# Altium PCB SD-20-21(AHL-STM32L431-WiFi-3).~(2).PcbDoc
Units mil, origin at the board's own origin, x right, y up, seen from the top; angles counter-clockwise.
Board outline 1905.3 x 2159.95 mil, 2 copper layers (Top Layer, Bottom Layer); 48 components, 77 nets, 281 pads, 181 vias.
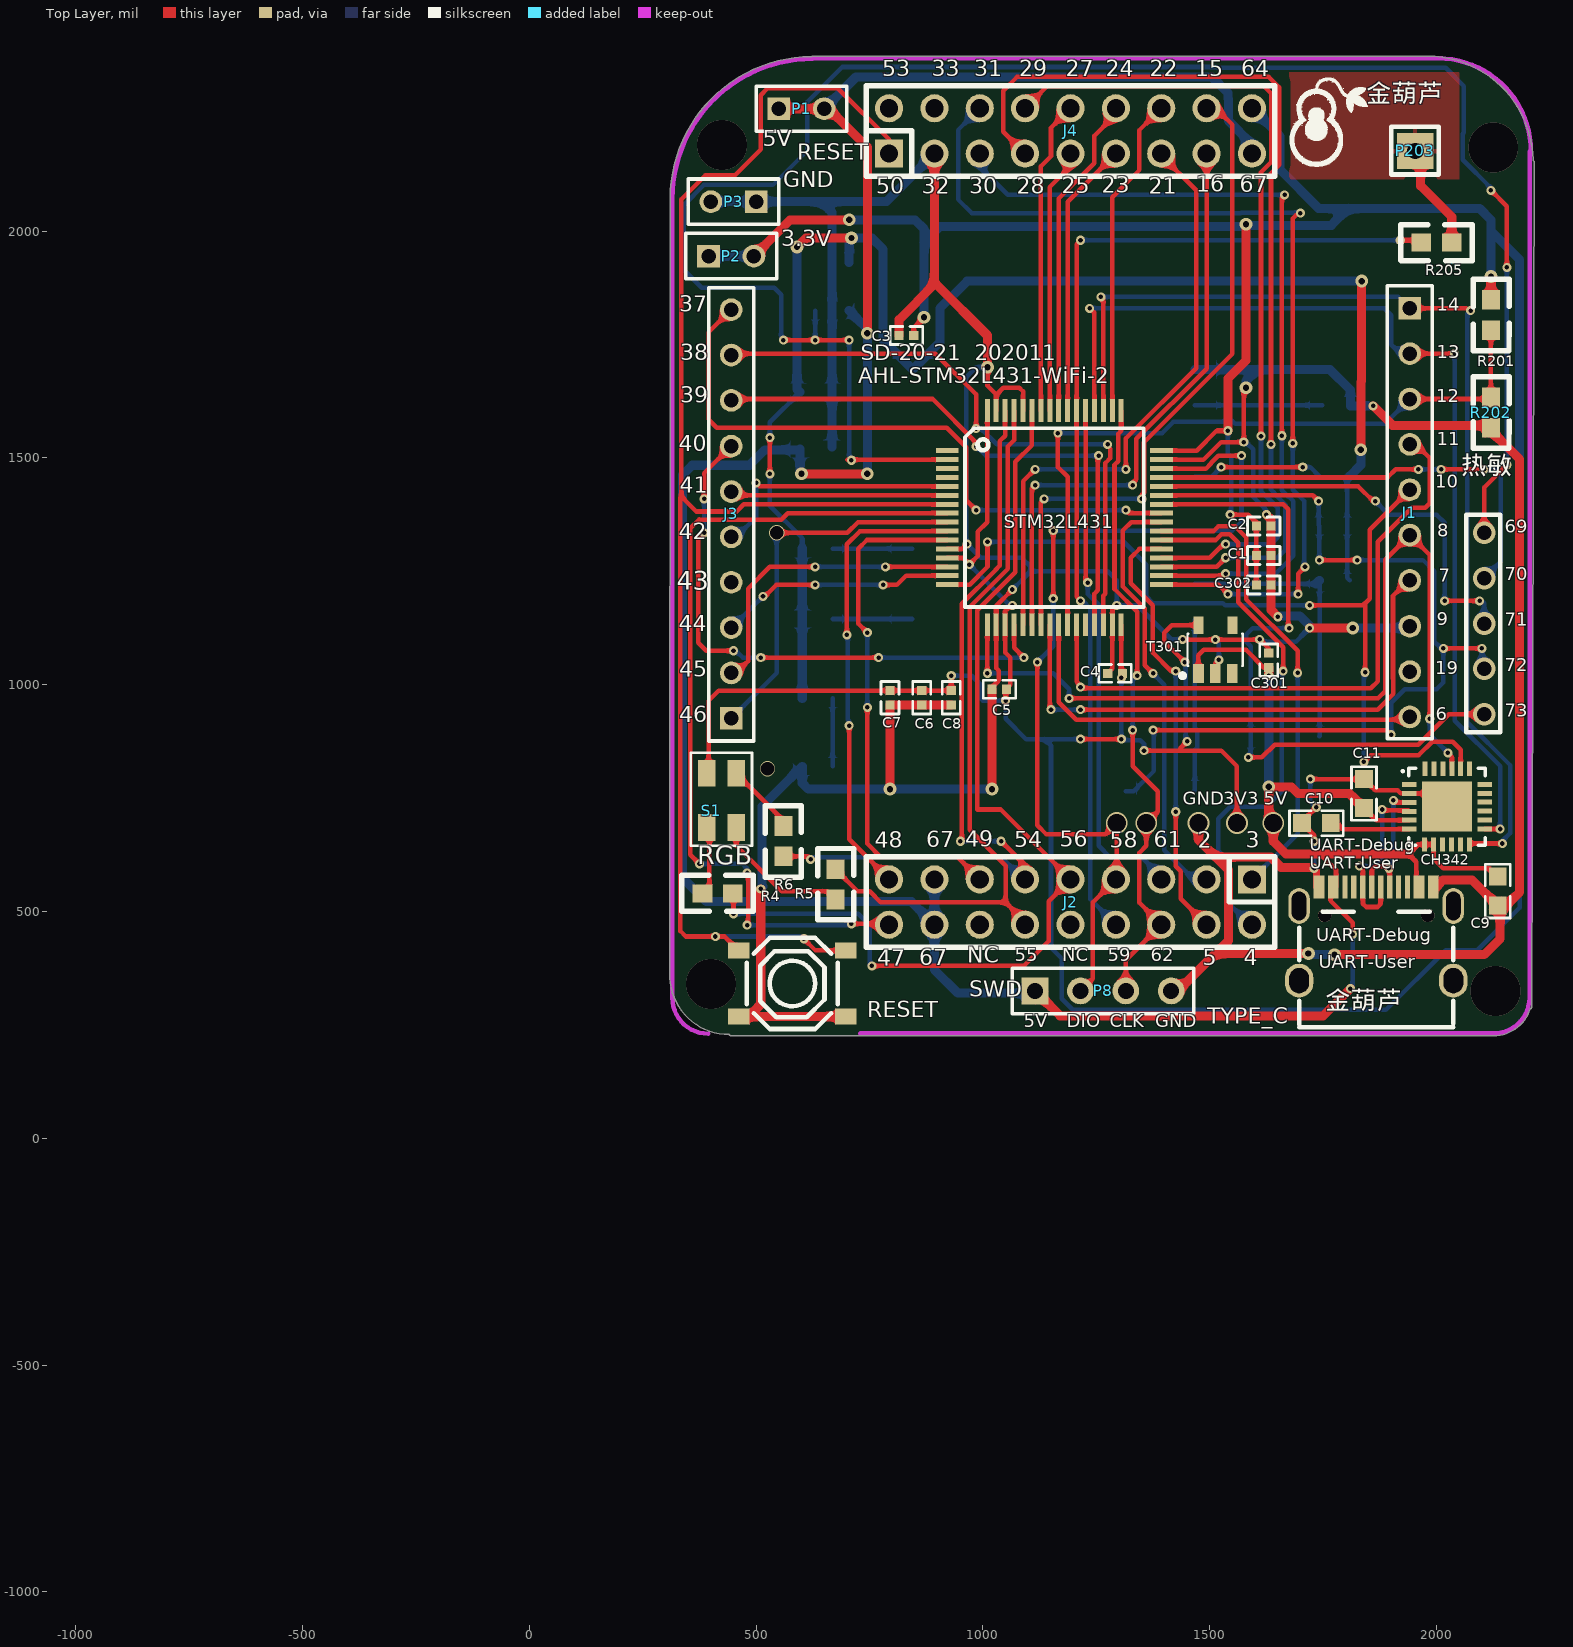
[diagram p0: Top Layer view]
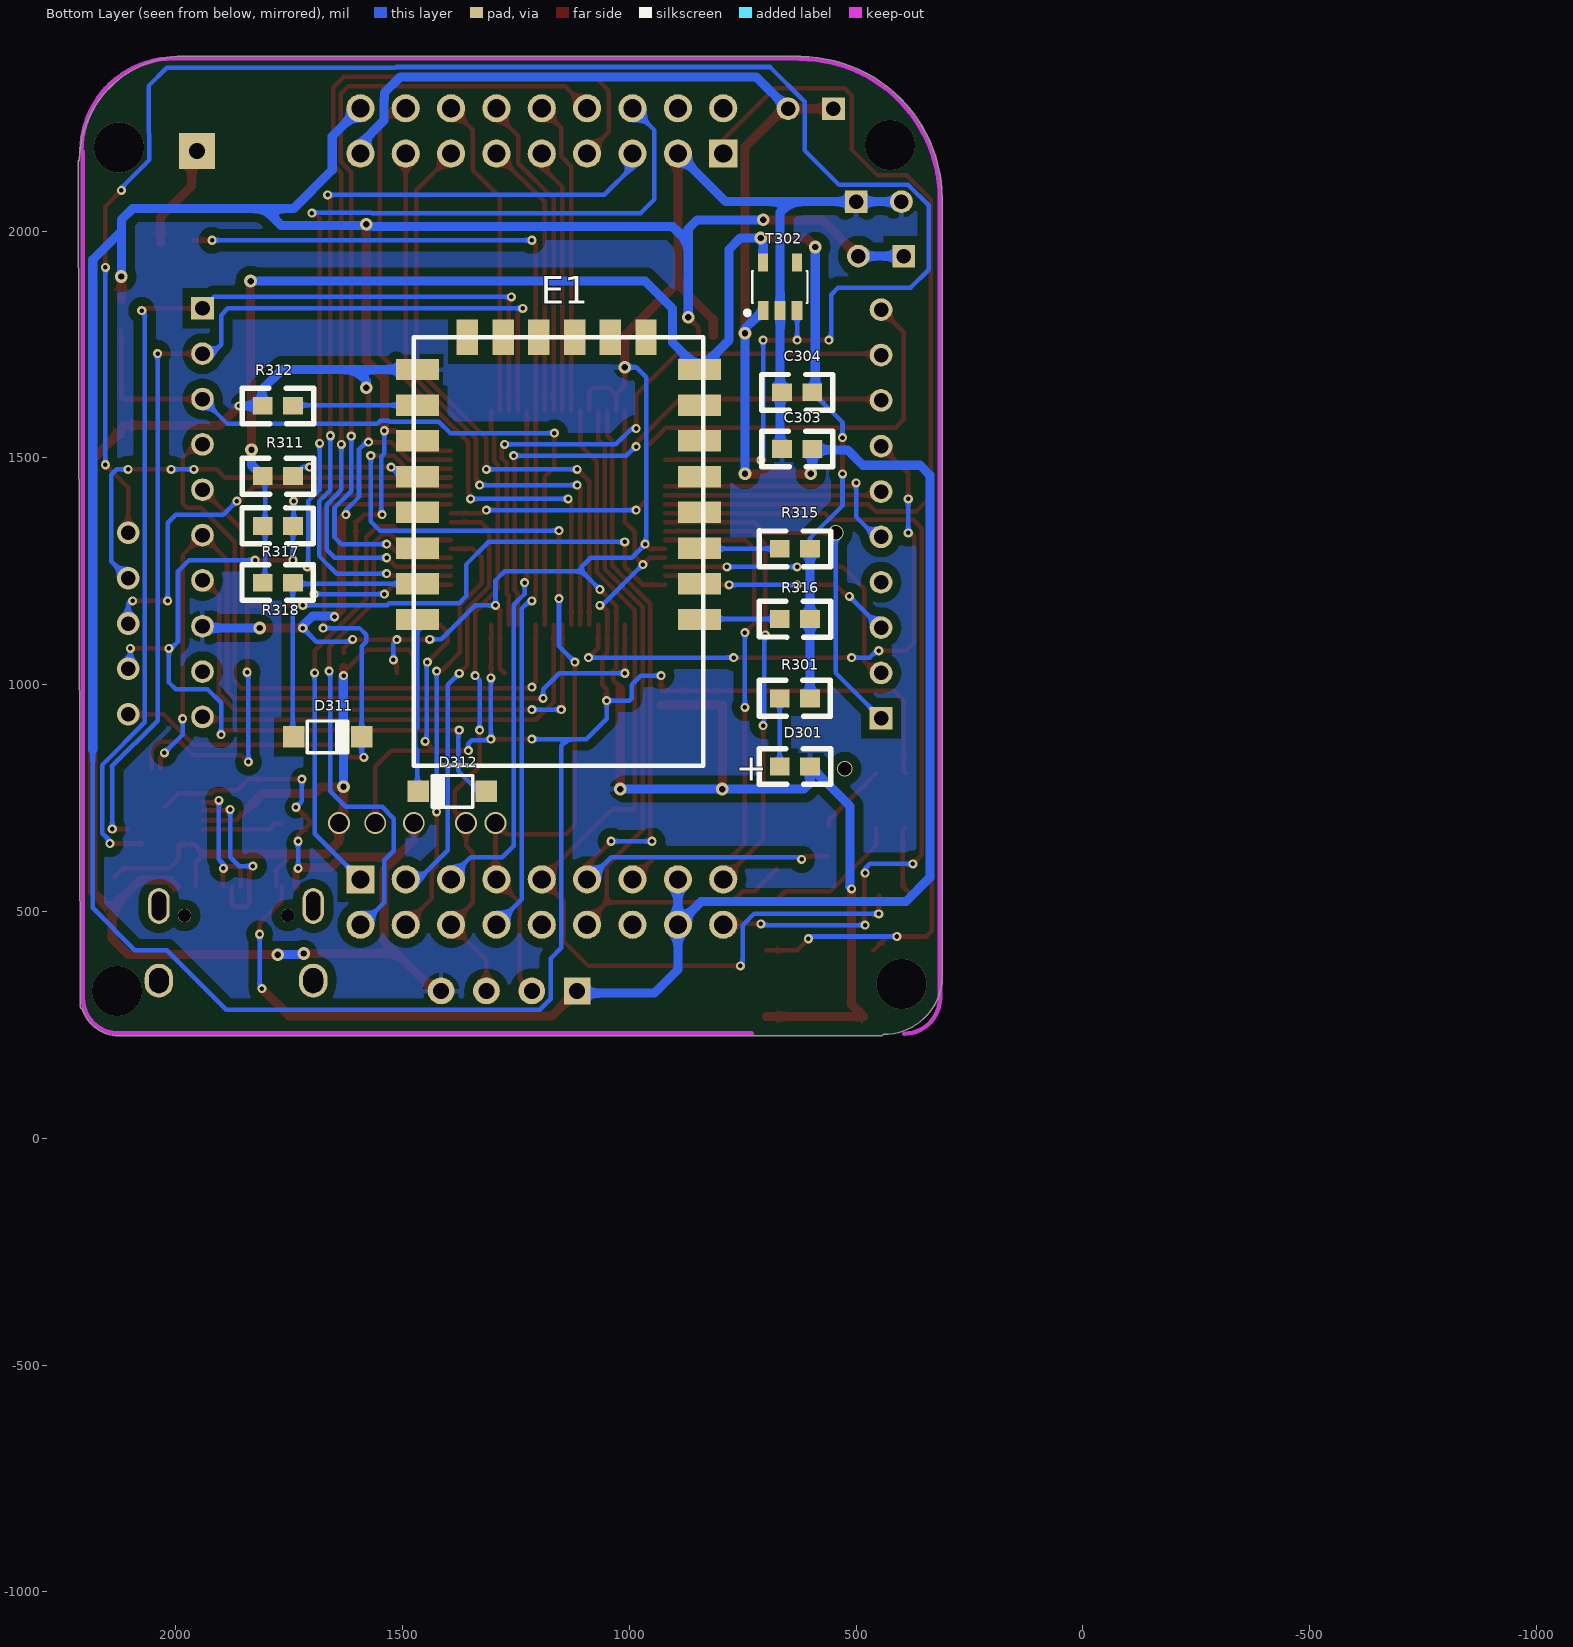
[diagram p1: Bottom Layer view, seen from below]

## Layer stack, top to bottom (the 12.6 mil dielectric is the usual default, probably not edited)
Top Solder: solder mask 0.4, Solder Resist, Dk 3.5
Top Layer: signal copper 1.4
Dielectric1: dielectric 12.6, FR-4, Dk 4.8
Bottom Layer: signal copper 1.4
Bottom Solder: solder mask 0.4, Solder Resist, Dk 3.5

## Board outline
309.97,365.12 ccw(c439.59,358.77) 440.44,229 ccw(c445,231.08) 445,226.07 2125.67,226.07 ccw(c2125.72,310.36) 2206.15,285.12 ccw(c2205,290) 2210.01,289.99 2215.26,2151.88 ccw(c2210.24,2151.89) 2215.26,2151.89 ccw(c2210.24,2151.89) 2212.77,2156.22 ccw(c1979.32,2152.54) 1980.39,2386.01 ccw(c1980.37,2381) 1979.86,2385.99 ccw(c1979.32,2381) 1979.32,2386.01 625,2386.01 ccw(c625,2381) 621.99,2385.01 ccw(c624.15,2071.15) 310.29,2071.96 ccw(c315.24,2071.2) 310.23,2071.2

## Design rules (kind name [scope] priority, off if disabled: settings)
Clearance Clearance_1 [All] p1: gap=7
HoleSize [All] p1: absolutevalues=TRUE maxlimit=200 minlimit=1 maxpercent=80.000 minpercent=20.000
MinimumSolderMaskSliver [All] p1: minsoldermaskwidth=0
PolygonConnect [All] p1: connectstyle=Relief reliefconductorwidth=10 reliefentries=4 polygonreliefangle="90 Angle" airgapwidth=10
RoutingVias [All] p1: holewidth=10 width=20 viastyle="Through Hole" minholewidth=10 minwidth=20 maxholewidth=10 maxwidth=20
SilkToSilkClearance [All] p1: silktosilkclearance=0
SilkToSolderMaskClearance [IsPad] p1: minsilkscreentomaskgap=0 clearancetoexposedcopper=TRUE
SolderMaskExpansion [All] p1: expansion=4
UnpouredPolygon [All] p1: allowunpoured=FALSE
Width [All] p1: maxlimit=20 minlimit=10 preferedwidth=10
25 further rules are at their usual default settings.

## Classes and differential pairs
component class 01_STM32L431_HardMinSys: C1 C5 C6 C7 C8 C9 STM32L431
component class 02_interface: C9 C301 C302 J1 J2 J3 P1 P2 P3 P203 R4 R5 R6 R201 R202 R205 S1 T301
component class 03_Wi-Fi-ESP8266: D201 D202 D301 R203 R204 R206 R301 T302

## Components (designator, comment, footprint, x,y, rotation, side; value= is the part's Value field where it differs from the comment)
C1 "Cap" 0402 1635,1285 r180 top (schematic designator C101)
C2 "Cap" 0402 1635,1350 r180 top (schematic designator C102)
C3 "Cap" 0402 815,1770 r0 top (schematic designator C103)
C4 "Cap" 0402 1275,1025 r0 top (schematic designator C104)
C5 "Cap" 0402 1020,990 r0 top (schematic designator C105)
C6 "Cap" 0402 865,955 r90 top (schematic designator C106)
C7 "Cap" 0402 795,955 r90 top (schematic designator C107)
C8 "Cap" 0402 930,955 r90 top (schematic designator C108)
C9 "Cap" 0603#1 2135,545 r270 top (schematic designator C4)
C10 "Cap" 0603#1 1735,695 r0 top (schematic designator C2)
C11 "Cap" 0603#1 1840,760 r90 top (schematic designator C3)
C301 "0402" 0402 1630,1070 r270 top
C302 "0402" 0402 1635,1220 r180 top
C303 "0402" 0603#2 630,1520 r180 bottom
C304 "0402" 0603#2 630,1645 r180 bottom
CH342 "ch342" ch342 1940,780 r0 top (schematic designator ch342)
D301 "LED3" 0603+ 635,820 r180 bottom
D311 "MBR0520" SOD-123 1665,885 r0 bottom
D312 "MBR0520" SOD-123 1390,765 r180 bottom
E1 "ESP8266" ESP8266 1475,1695 r180 bottom
J1 "J1-2" HDR1X10#1 1941,1830 r270 top locked
J2 "J2-2" IDC2X9 1593,571 r180 top
J3 "J3-2" HDR1X10#2 445,926 r90 top locked
J4 "J4-2" IDC2X9 793,2171 r0 top
P1 "5V" HDR1X2 550,2270 r0 top
P2 "3.3V" HDR1X2 395,1945 r0 top
P3 "GND" HDR1X2 500,2065 r180 top
P8 "SWD接口" HDR1X4 1115,325 r0 top
P203 "TSI触摸键" TSI 1995,2130 r90 top
R4 "Res2" 0603#2 415,540 r180 top
R5 "Res2" 0603#2 675,560 r90 top
R6 "Res2" 0603#2 560,655 r270 top
R201 "Res2" 0603#2 2120,1815 r90 top
R202 "热敏" 0603#2 2120,1600 r90 top
R205 "Res2" 0603#2 2000,1975 r0 top
R301 "Res2" 0603#2 635,970 r0 bottom
R311 "Res2" 0603#2 1775,1460 r180 bottom
R312 "Res2" 0603#2 1775,1615 r180 bottom
R315 "*" 0603#2 635,1300 r180 bottom
R316 "*" 0603#2 635,1145 r180 bottom
R317 "Res2" 0603#2 1775,1350 r0 bottom
R318 "Res2" 0603#2 1775,1225 r0 bottom
RESET "复位按钮" RESET_KEY 560,365 r0 top (schematic designator RESET_1)
S1 "Single-Pole, Single-Throw Switch" LED3 420,750 r90 top
STM32L431 "STM32" LQFP64 1000,1530 r0 top
T301 "SOT-23-5" SOT-23-5 1515,1085 r0 top
T302 "SOT-23-5" SOT-23-5 665,1885 r180 bottom
TYPE_C "TYPE-C-31-M-12" TYPE_C 1865,420 r0 top (schematic designator TAPE_C)

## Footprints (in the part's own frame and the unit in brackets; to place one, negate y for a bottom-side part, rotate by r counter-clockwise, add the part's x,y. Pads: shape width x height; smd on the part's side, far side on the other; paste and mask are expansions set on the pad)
0402 [mm]
  rect 0.51x0.51 smd: 1(0,0) 2(0.82,0)
  silkscreen extent -0.5,-0.5 1.32,0.5
0603#1 [mm]
  rect 1x1 smd: 1(-0.81,0) 2(0.81,0)
  silkscreen extent -1.5,-0.7 1.5,0.7
0603#2 [mm]
  rect 1.1x1 smd: 1(-0.85,0) 2(0.85,0)
  silkscreen extent -1.99,-1.01 2,0.99
0603+ [mm]
  rect 1.1x1 smd: 1(-0.85,0) 2(0.85,0)
  silkscreen extent -1.99,-1.01 2,0.99
ch342 [mm]
  rect 2.8x2.8 smd: 0(2.108,-1.232)
  rect 0.8x0.28 smd: 1(0,0) 2(0,-0.5) 3(0,-1.001) 4(0,-1.499) 5(0,-1.999) 6(0,-2.499) 13(4.216,-2.489) 14(4.216,-1.989) 15(4.216,-1.488) 16(4.216,-0.991) 17(4.216,-0.49) 18(4.216,0.01)
  rect 0.28x0.8 smd: 7(0.864,-3.353) 8(1.364,-3.353) 9(1.864,-3.353) 10(2.362,-3.353) 11(2.863,-3.353) 12(3.363,-3.353) 19(3.378,0.889) 20(2.878,0.889) 21(2.377,0.889) 22(1.88,0.889) 23(1.379,0.889) 24(0.879,0.889)
  silkscreen extent -0.37,-3.39 4.26,0.91
ESP8266 [mm]
  rect 2.4x1.2 smd: 1(0.2,0) 2(0.2,-2) 3(0.2,-4) 4(0.2,-6) 5(0.2,-8) 6(0.2,-10) 7(0.2,-12) 8(0.2,-14) 9(16,-14) 10(16,-12) 11(16,-10) 12(16,-8) 13(16,-6) 14(16,-4) 15(16,-2) 16(16,0)
  rect 1.2x2 smd: 17(13,1.8) 18(11,1.8) 19(9,1.8) 20(7,1.8) 21(5,1.8) 22(3,1.8)
  silkscreen extent 0,-22.2 16.2,1.8
HDR1X2 [mil]
  rect 50x50 hole 32: 1(0,0)
  round 50 hole 32: 2(100,0)
  silkscreen extent -50,-50 150,50
HDR1X4 [mm] "Connector; Header; 4 Position"
  rect 1.5x1.5 hole 0.9: 1(0,0)
  round 1.5 hole 0.9: 2(2.54,0) 3(5.08,0) 4(7.62,0)
  silkscreen extent -1.27,-1.27 8.89,1.27
HDR1X10#1 [mil]
  rect 50x50 hole 32: 1(0,0)
  round 50 hole 32: 2(100,0) 3(200,0) 4(300,0) 5(400,0) 6(500,0) 7(600,0) 8(701,0) 9(801,0) 10(901,0)
  silkscreen extent -50,-50 949,50
HDR1X10#2 [mil]
  rect 50x50 hole 32: 1(0,0)
  round 50 hole 32: 2(100,0) 3(200,0) 5(400,0) 6(500,0) 7(600,0) 8(701,0) 9(801,0) 10(901,0)
  round 50 hole 32 paste+0: 4(300,0)
  silkscreen extent -50,-50 949,50
IDC2X9 [mil]
  round 62 hole 40: 1(0,100) 3(100,100) 4(100,0) 5(200,100) 6(200,0) 7(300,100) 8(300,0) 9(400,100) 10(400,0) 11(500,100) 12(500,0) 13(600,100) 14(600,0) 15(700,100) 16(700,0) 17(800,100) 18(800,0)
  rect 62x62 hole 40: 2(0,0)
  silkscreen extent -50,-50 850,150
LED3 [mil]
  round 40 on Top Overlay: 0(-110,74)
  rect 59.06x39.37 smd: 1(-65,29) 2(55,29) 3(55,-36) 4(-65,-36)
  silkscreen extent -105,-71 100,64
LQFP64 [mm]
  rect 1.27x0.28 smd: 1(-2.007,-0.356) 2(-2.007,-0.856) 3(-2.007,-1.356) 4(-2.007,-1.856) 5(-2.007,-2.356) 6(-2.007,-2.856) 7(-2.007,-3.356) 8(-2.007,-3.856) 9(-2.007,-4.356) 10(-2.007,-4.856) 11(-2.007,-5.356) 12(-2.007,-5.856) 13(-2.007,-6.356) 14(-2.007,-6.856) 15(-2.007,-7.356) 16(-2.007,-7.856) 33(9.993,-7.856) 34(9.993,-7.356) 35(9.993,-6.856) 36(9.993,-6.356) 37(9.993,-5.856) 38(9.993,-5.356) 39(9.993,-4.856) 40(9.993,-4.356) 41(9.993,-3.856) 42(9.993,-3.356) 43(9.993,-2.856) 44(9.993,-2.356) 45(9.993,-1.856) 46(9.993,-1.356) 47(9.993,-0.856) 48(9.993,-0.356)
  rect 0.28x1.27 smd: 17(0.243,-10.106) 18(0.743,-10.106) 19(1.243,-10.106) 20(1.743,-10.106) 21(2.243,-10.106) 22(2.743,-10.106) 23(3.243,-10.106) 24(3.743,-10.106) 25(4.243,-10.106) 26(4.743,-10.106) 27(5.243,-10.106) 28(5.743,-10.106) 29(6.243,-10.106) 30(6.743,-10.106) 31(7.243,-10.106) 32(7.743,-10.106) 49(7.743,1.894) 50(7.243,1.894) 51(6.743,1.894) 52(6.243,1.894) 53(5.743,1.894) 54(5.243,1.894) 55(4.743,1.894) 56(4.243,1.894) 57(3.743,1.894) 58(3.243,1.894) 59(2.743,1.894) 60(2.243,1.894) 61(1.743,1.894) 62(1.243,1.894) 63(0.743,1.894) 64(0.243,1.894)
  silkscreen extent -1.01,-9.11 8.99,0.89
RESET_KEY [mil]
  rect 47.2x35.4 smd: 1(-98.4,49.2)
  rect 47.2x35.5 smd: 2(137.82,49.25) 3(-98.4,-96.45) 4(137.82,-96.45)
  silkscreen extent -81,-124 120,77
SOD-123 [mm]
  rect 1.2x1.2 smd: 1(1.905,0) 2(-1.905,0)
  silkscreen extent -1.14,-0.89 1.14,0.89
SOT-23-5 [mm]
  rect 0.6x1.05 smd: 1(-1.016,-1.524) 2(-0.066,-1.524) 3(0.884,-1.524)
  rect 0.55x1 smd: 4(0.884,1.176) 5(-1.016,1.176)
  silkscreen extent -2.03,-1.78 1.47,0.7, body extent -1.5,-1.53 1.4,1.27, height 1.09
TSI [mil]
  rect 80x80 hole 35.43: 1(47,42)
  silkscreen extent -5,-10 100,95
TYPE_C [mm]
  oval 1.2x2 hole 0.8 slot 1.6 at 90 deg: 1(-4.269,2.343) 4(4.371,2.343)
  oval 1.6x1.9 hole 1.1 slot 1.4 at 90 deg: 2(-4.269,-1.837) 3(4.371,-1.837)
  rect 0.3x1.3 smd: A1(-3.299,3.411) A4(-2.499,3.411) A5(-1.199,3.411) A6(-0.199,3.411) A7(0.301,3.411) A8(1.3,3.412) A9(2.601,3.411) A12(3.401,3.411) B1(3.101,3.411) B4(2.301,3.411) B5(1.801,3.411) B6(0.801,3.411) B7(-0.699,3.411) B8(-1.699,3.412) B9(-2.199,3.411) B12(-2.999,3.411)
  round 0.75 hole 0.75 unplated: ""(-2.839,1.813) ""(2.941,1.813)
  silkscreen extent -4.27,-4.44 4.37,2.01

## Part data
C1 C2 C3 C4 C5 C6 C7 C8 C9 C10 C11: "Capacitor"
C301 C302 C303 C304: library part Cap, "Capacitor"
D301: "Typical BLUE SiC LED"
J1 J3: library part "Header 10", "Header, 10-Pin"
J2 J4: library part CON2X9
P1 P2 P3: library part "Header 2", "Header, 2-Pin"
P8: library part "Header 4", "Header, 4-Pin"
P203: library part Plug, "Plug"
R4 R5 R6 R201 R205 R301 R311 R312 R317 R318: "Resistor"
R202: library part Res1, "Resistor"
R315 R316: library part Res2, "Resistor"
RESET: library part RESET
S1: library part LED_3
T301 T302: "TPS70933"

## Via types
v1: diameter 20, hole 10, Top Layer to Bottom Layer, 146 vias
v2: diameter 28, hole 14, Top Layer to Bottom Layer, 19 vias
v3: diameter 47.99, hole 40, Top Layer to Bottom Layer, 5 vias
v4: diameter 50, hole 32, Top Layer to Bottom Layer, 5 vias
v5: diameter 110.11, hole 110.11, Top Layer to Bottom Layer, 4 vias
v6: diameter 34, hole 30, Top Layer to Bottom Layer, 2 vias

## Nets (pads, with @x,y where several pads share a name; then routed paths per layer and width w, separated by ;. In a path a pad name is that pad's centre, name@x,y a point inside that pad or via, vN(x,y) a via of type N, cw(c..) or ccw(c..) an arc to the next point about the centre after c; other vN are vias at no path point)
DN2: CH342.4 TYPE_C.A7 TYPE_C.B7 | length 393.3
  Top Layer w10: v1(1830,600) 1837.47,592.53 TYPE_C.B7 1837.47,517.53 1845,510 1870,510 1876.84,516.84 TYPE_C.A7 ; v1(1880,725) 1882,723 1914.11,723 1914.2,723.09 1937.91,723.09 CH342.4
  Bottom Layer w10: v1(1830,600) 1860,600 1880,620 v1(1880,725)
DP2: CH342.3 TYPE_C.A6 TYPE_C.B6 | length 317.5
  Top Layer w10: TYPE_C.A6 1857.16,592.16 1865,600 1890,600 1896.53,593.47 TYPE_C.B6 ; v1(1905,745) 1909.4,740.6 CH342.3
  Bottom Layer w10: v1(1895,595) 1890,600 1905,615 v1(1905,745)
GND: C1.1 C2.1 C3.1 C4.1 C5.1 C6.1 C7.1 C8.1 C9.2 C10.1 C11.2 C301.1 C302.1 C303.1 C304.1 CH342.0 CH342.2 D301.2 E1.1 J1.8 J4.4 P3.1 P3.2 P8.4 R202.1 R312.1 RESET.3 RESET.4 STM32L431.12 STM32L431.18 STM32L431.31 STM32L431.47 STM32L431.60 STM32L431.63 T301.2 T302.2 TYPE_C.A1 TYPE_C.A12 TYPE_C.B1 TYPE_C.B12 | length 10800.7
  Top Layer w10: STM32L431.12 954.46,1299.46 v1(965,1310) ; v2(1010,1700) 1010,1659.27 1029.27,1640 1029.27,1639.27 ; C5.1@1020,994.77 1035,1009.77 1035,1031.11 1029.27,1036.84 STM32L431.18 1029.27,1174.27 v1(1065,1210) ; STM32L431.63 1029.27,1639.27 ; STM32L431.60 1088.32,1646.68 1080,1655 1045,1655 1029.27,1639.27 ; C4.1 1285.17,1035.17 STM32L431.31 1285.17,1165.17 v1(1295,1175) ; STM32L431.47 1486.16,1496.32 1524.85,1535 v1(1575,1535) 1575,1650 v2(1580,1655) ; v1(1440,1100) 1440.39,1099.61 v1(1512.39,1099.61) 1609.61,1099.61 v1(1610,1100) 1630,1080 C301.1 ; T301.2 1512.4,1047.4 v1(1520,1055) ; v1(1721.89,791.89) C11.2 1864.89,767 1914.77,767 1921.47,760.3 CH342.2 1994.2,760.3 CH342.0 ; v1(1730,655) 1730,668.11 C10.1 1703.11,698.11 v1(1735,730) ; C9.2@2126.17,504.28 C9.2
  Top Layer w15: v1(1730,595) 1735.11,589.89 TYPE_C.A1
  Top Layer w20: v1(510,550) 510,295 483.55,268.55 RESET.4 ; v2(795,770) C7.1 C6.1 C8.1 ; C3.1 815,1805 893,1883 ; J4.4 893,1883 ; v2(1010,1700) 1010,1770 897,1883 893,1883 ; v2(1020,770) C5.1 ; P8.4 1430,325 1512.5,407.5 ; v3(1475,695) 1475,657.88 1512.88,620 ; v1(1625,1375) 1635,1365 C2.1 C1.1 C302.1 1635,1165 v1(1650,1150) ; v2(1717.5,407.5) 1512.5,407.5 ; v1(1720,1125) v2(1815,1125) ; v1@1727.5,597.5 1657.5,597.5 1635,620 1512.88,620 ; v2(1775,405) 2105,405 2140,440 2140,508.11 C9.2 ; v1(1860,1615) 1903,1572 2114.54,1572 R202.1 2120,1560 2183,1497 2183,543 2153.11,513.11 C9.2 ; TYPE_C.A12 2014.61,570 2078.11,570 C9.2 ; 1512.5,407.5 1541,436 1541,591.88 1512.88,620
  Bottom Layer w10: v2(1010,1700) 985,1700 963,1678 963,1312 v1(965,1310) 995,1280 1085,1280 1105,1260 1105,1250 ; v1(1065,1210) 1105,1250 ; v1(1440,1100) 1415,1100 1340,1175 v1(1295,1175) 1295,1230 1275,1250 1105,1250 ; v1(1512.39,1099.61) 1520,1092 v1(1520,1055) ; v1(1575,1535) 1580,1535 1596,1519 1596,1414 1625,1385 v1(1625,1375) ; v1@1610,1095 1690,1095 v1(1720,1125) ; v1(1721.89,791.89) 1721.89,743.11 v1(1735,730) ; v1(1730,595) v1(1730,655)
  Bottom Layer w20: P3.2 P3.1 643.5,2065 ; v1@515,555 513.27,556.73 513.27,731.73 D301.2 601.53,783.47 615,770 v2@790,770 ; C303.1@667.6,1524.13 T302.2 667.6,2040.9 643.5,2065 ; v2(795,770) v2@1010,770 ; J4.4 787,2065 643.5,2065 ; E1.1 1605,1695 ; v2(1580,1655) 1580,1670 1605,1695 ; v1(1650,1150) 1652,1152 1698,1152 1720,1130 v1(1720,1125) ; v2(1717.5,407.5) 1720,405 v2(1775,405) ; v2(1815,1125) 1937,1125 J1.8 ; v1@1850,1615 1810,1615 1810,1650 1765,1695 1605,1695
GNSS-ANT: J1.9
GSM-ANT: J4.3
NC: J2.13
NetC10_2: C10.2 CH342.6 | length 178.7
  Top Layer w10: C10.2 1780,695 1793.4,681.6 CH342.6
NetC109_2: STM32L431.4
NetC110_2: STM32L431.3
NetD201_2: 
NetD202_1: 
NetD301_1: D301.1 R301.2 | length 150
  Bottom Layer w10: D301.1 R301.2
NetD311_1: D311.1 E1.7 R318.1 | length 616.3
  Bottom Layer w10: E1.7 R318.1@1734.09,1222.56 ; D311.1@1741.54,886.54 1742,887 1742,1224.54 R318.1
  Bottom Layer w20: R318.1@1734.09,1222.56 R318.1@1741.54,1230
NetD312_2: D312.2 E1.8 | length 383.7
  Bottom Layer w10: D312.2 1467.13,767.13 1467.13,856.14 1472,861.01 1472,900.13 1467.13,905 E1.8
NetE1_2: E1.2 R312.2 | length 281
  Bottom Layer w10: E1.2 R312.2@1748.15,1616.26
NetE1_4: E1.4 R311.2 | length 281.5
  Top Layer w10: v1(1525,1480) v1@1695,1480
  Bottom Layer w10: E1.4 1503.78,1458.78 v1(1525,1480) ; v1(1705,1480) 1721.53,1480 R311.2
NetE1_9: E1.9 R316.1 | length 175.4
  Bottom Layer w10: R316.1 E1.9@843.9,1145
NetE1_11: E1.11 R315.1 | length 175.3
  Bottom Layer w10: R315.1 E1.11@843.78,1300
NetP203_1: P203.1 R205.2 | length 218.4
  Top Layer w20: P203.1@1965,2165 1965,2100 2033.47,2031.53 R205.2
NetR4_2: R4.2 S1.1 | length 158.9
  Top Layer w10: R4.2@381.54,535 R4.2 397,555.46 397,679 S1.1
NetR5_1: R5.1 S1.4 | length 307.8
  Top Layer w10: S1.4 456,645.54 556.54,545 656.54,545 R5.1
NetR6_1: R6.1 S1.3 | length 159.6
  Top Layer w10: S1.3 560,701 R6.1
P3V3: C1.2 C2.2 C3.2 C4.2 C5.2 C6.2 C7.2 C8.2 C302.2 J4.17 P2.1 P2.2 R201.2 S1.2 STM32L431.13 STM32L431.19 STM32L431.32 STM32L431.48 STM32L431.64 T301.5 | length 9790.8
  Top Layer w10: S1.2 395,809 395,965 417.28,987.28 C7.2 C6.2 C8.2 930,1010 ; C3.2 847.28,1787.28 v2(870,1810) ; STM32L431.13 955.22,1279.78 v1(970,1265) 988,1283 988,1337 1009.58,1358.58 STM32L431.64 ; v1(1050,965) 1050,990 1060,1000 1060,1060 1048.95,1071.05 STM32L431.19 1048.95,1162.96 v1@1060.99,1175 ; v1(1215,880) v1(1305,880) ; C4.2@1304.86,1027.43 STM32L431.32 ; v1(1355,855) 1435,855 ; STM32L431.48 1471,1516 1515,1560 v1(1540,1560) ; v1@1440,1055 1400,1095 1400,1115 1416.3,1131.3 T301.5 ; v1(1450,875) 1435,860 1435,855 ; v1(1545,1375) 1585,1375 1602.72,1357.28 C2.2 C1.2 C302.2 ; v3(1560,695) 1560,820 1525,855 1435,855
  Top Layer w20: P2.2 575,2025 v2(705,2025) ; v1(1540,1560) 1540,1675 1580,1715 v2(1580,2015) v2@1581,2015 ; R201.2 v2(2120,1900)
  Bottom Layer w10: v1(930,1020) 975,1020 995,1000 995,970 1000,965 v1(1050,965) 1050,925 1095,880 1135,880 ; v1(970,1265) 1055,1180 v1@1060,1180 ; v1(1215,880) 1135,880 ; v1(1305,1015) v1(1305,880) 1307,878 1347,878 1355,870 v1(1355,855) ; v1(1445,1050) 1447,1048 v1@1447,883 ; v1(1540,1560) 1540,1510 1547,1503 1547,1377 v1(1545,1375) ; 2183,857 2183,508 2090,415 2020,415 1888.47,283.47 1197.8,283.47 1173.47,307.8 1173.47,396.53 1150,420 1150,865 1135,880
  Bottom Layer w20: P2.1 P2.2 ; v2(705,2025) 850,2025 870,2005 870,1975 ; v2(870,1810) 870,1975 ; J4.17 1655,2209 1655,2135 1740,2050 1805,2050 ; v2(2120,1900) 2120,1995 ; 2183,857 2183,1937 2125,1995 2120,1995 ; 870,1975 905,2010 1575,2010 v2(1580,2015) 1582,2013 1768,2013 1805,2050 ; 1805,2050 2095,2050 2120,2025 2120,1995
  other v1: 1065,1175
P3V3_ME: C304.2 E1.16 R301.1 R311.1 R315.2 R316.2 R317.2 R318.2 T302.5 | length 3401.5
  Top Layer w10: v1(530,1465) v1(530,1545)
  Top Layer w20: v2(590,1965) 610,1985 v2(710,1985) ; v2(1833,1518) 1833,1668 1835,1670 v2(1835,1890)
  Bottom Layer w10: v1(530,1465) 530,1395 601.53,1323.47 R315.2 ; v1(530,1545) 530,1578.47 C304.2 ; R311.1@1803,1454.54 1803,1235.47 R318.2@1808.46,1230
  Bottom Layer w20: v2(590,1965) 590,1651.53 C304.2 ; R301.1 R315.2 ; T302.5 705,1980 v2(710,1985) 755,1985 780,1960 780,1760.08 E1.16 845.08,1695.08 905,1755 905,1830 965,1890 v2(1835,1890) ; R311.1@1803,1454.54 R311.1 1833,1484.54 v2(1833,1518)
P3V9: 
P5V: C9.1 C11.1 C301.2 C303.2 CH342.5 CH342.7 CH342.8 J2.15 J2.16 J4.18 P1.1 P1.2 P8.1 T301.1 T302.1 TYPE_C.A4 TYPE_C.A9 TYPE_C.B4 TYPE_C.B9 | length 7172.7
  Top Layer w10: T301.1 1475,1065 1487,1077 1580,1077 1619.28,1037.72 C301.2 ; 1745,625 1766.61,603.39 1778.42,591.58 TYPE_C.B9 ; TYPE_C.A4 1766.61,523.39 1815,475 v1(1815,450) ; C11.1 1866.81,701.3 CH342.5 ; TYPE_C.B4 1955.58,609.42 1938,627 1959,648 CH342.7 CH342.8 1993.7,616.3 2015,595 2116.89,595 C9.1
  Top Layer w20: P1.1 P1.2 660,2270 745,2185 v2@745,1785 ; v2(600,1465) v2(745,1465) ; P8.1 1170,270 1750,270 v1(1810,330) ; v1(1630,1020) C301.2 ; C11.1 1808.11,760 1695,760 1680,775 v2(1630,775) 1630,705 v3(1640,695) 1640,655 1668,627 1938,627
  Bottom Layer w10: v1(1810,330) 1815,335 v1(1815,450)
  Bottom Layer w20: v2@596.53,1468.47 C303.2 594.53,1518 519,1518 485,1484 359,1484 337.25,1462.25 337.25,575 390.25,522 842,522 J2.15 ; P1.2@650,2265 P1.2 720,2340 1505,2340 1540,2305 1540,2292.88 1541,2291.88 1541,2244 1593,2192 J4.18 ; T302.1 745,1785 v2(745,1775) v2(745,1465) ; J2.16 J2.15 ; P8.1 1110,320 945,320 893,372 J2.15 ; v2(1630,775) 1630,853.09 1630.62,853.71 1630.62,1019.38 v1(1630,1020)
PTA0: J3.2 STM32L431.14 | length 666.7
  Top Layer w10: J3.2 456,1026 482,1052 482,1212 530.09,1260.09 v1(630,1260.09) ; v1(785,1260.09) STM32L431.14
  Bottom Layer w10: v1(630,1260.09) v1(785,1260.09)
PTA1: J3.3 STM32L431.15 | length 522.5
  Top Layer w10: v1@517,1192.41 544.59,1220 v1(630,1220) ; v1(780,1220) 810,1220 830.41,1240.41 STM32L431.15
  Bottom Layer w10: J3.3 446,1126 v1(515,1195) ; v1(630,1220) v1(780,1220)
PTA2: CH342.20 J1.5 STM32L431.16 | length 2016.6
  Top Layer w10: STM32L431.16 970.72,1220.72 1010,1260 v1(1010,1315) ; v1(1720,1175) 1836.88,1175 1841.88,1180 1842.44,1179.44 ; v1(1840,830) 1855,845 1961.04,845 1990.52,874.48 2035.52,874.48 2053.3,856.7 CH342.20 ; v1(1842.44,1027.56) 1842.44,1179.44 ; J1.5 1853,1342 1853,1190 1842.44,1179.44
  Bottom Layer w10: v1(1010,1315) 1310,1315 1360,1265 1360,1195 1375,1180 1528.89,1180 1533.89,1175 v1(1720,1175) ; v1(1840,830) 1840,1025.12 v1(1842.44,1027.56)
PTA3: CH342.21 J1.6 STM32L431.17 | length 1945.1
  Top Layer w10: v1(1009.58,1025.42) STM32L431.17 ; v1(1190,970) 1870.96,970 1887,986.04 1887,1276 J1.6 1985,1286 v1(1985,925) ; v1(2025,850) 2033.6,841.4 CH342.21
  Bottom Layer w10: v1(1009.58,1025.42) 1154.58,1025.42 1190,990 v1(1190,970) ; v1(1985,925) 1985,890 v1(2025,850)
PTA4: J3.7 STM32L431.20 | length 1271.8
  Top Layer w10: v1@380,1335 372,1327 372,1093 390,1075 v1(450,1075) ; v1(385,1410) 385,1466 J3.7 ; v1(510,1060) v1(770,1060) ; STM32L431.20 1068.64,1081.36 v1(1090,1060)
  Bottom Layer w10: v1(385,1335) 385,1400 ; v1(450,1075) 455,1075 470,1060 v1(510,1060) ; v1@762,1060 v1(770,1060) v1(1090,1060)
PTA5: J4.14 STM32L431.21 | length 1346
  Top Layer w10: STM32L431.21 1088.32,1448.32 v1(1115,1475) ; v1(1315,1475) 1315,1543.08 1470,1698.08 1470,2090 1393,2167 J4.14
  Bottom Layer w10: v1(1115,1475) v1(1315,1475)
PTA6: J4.16 STM32L431.22 | length 1324.3
  Top Layer w10: STM32L431.22 1108.01,1433.01 v1(1115,1440) ; v1(1330,1440) 1330,1445 1338,1453 1338,1542.04 1493,1697.04 J4.16
  Bottom Layer w10: v1(1115,1440) v1(1330,1440)
PTA7: J4.15 STM32L431.23 | length 1465.3
  Top Layer w10: STM32L431.23 1127.69,1402.69 ; v1(1350,1410) 1350,1418.56 1355,1423.56 1355,1535 1550,1730 1550,2235 1514,2271 J4.15
  Bottom Layer w10: v1(1135,1410) v1(1350,1410)
PTA8: J3.10 STM32L431.41 | length 1415.3
  Top Layer w10: J3.10 395,1777 395,1585 413,1567 920,1567 963,1524 963,1407 v1(985,1385) ; v1(1315,1385) 1321.8,1378.2 STM32L431.41
  Bottom Layer w10: v1(985,1385) v1(1315,1385)
PTA9: D311.2 STM32L431.42 | length 1481.6
  Top Layer w10: STM32L431.42 1662.11,1397.89 1673,1387 1673,1127 v1(1675,1125) ; v1(1585,840) 1615,840 1643,868 1960,868 2027,935 v4(2105,935)
  Bottom Layer w10: v1(1585,840) v1@1590,840 ; v1@1590,845 D311.2 1590,1085 1580,1095 1580,1110 1595,1125 v1(1675,1125)
PTA10: D312.1 R317.1 STM32L431.43 | length 2038.1
  Top Layer w10: v1(1375,900) 1890,900 v1(1900,890) ; STM32L431.43 1727.43,1417.57 v1(1740,1405) ; v1(1741.54,1275) v1(1825,1275) ; v1(2015,1080) v1@2095,1080
  Bottom Layer w10: D312.1 1332,765 1377,810 1377,898 v1(1375,900) ; R317.1@1740,1351.54 v1(1740,1405) ; v1@1741.54,1268.46 v1(1741.54,1275) R317.1 ; v1(1825,1275) 1970,1275 1995,1250 1995,1095 2010,1080 v1(2015,1080) 2015,1005 2000,990 1930,990 1900,960 v1(1900,890) ; v1(2100,1080) 2100,1040 v4(2105,1035)
PTA11: STM32L431.44 | length 948.9
  Top Layer w10: STM32L431.44 1827.74,1437.26 v1@1860,1405 ; v1(2018,1185) v1@2085,1185
  Bottom Layer w10: v1(1865,1405) 1895,1375 2000,1375 2018,1357 v1(2018,1185) ; v1(2095,1185) 2100,1185 2105,1180 v4(2105,1135)
PTA12: STM32L431.45 | length 989.3
  Top Layer w10: STM32L431.45 1891.94,1456.94 1910,1475 v1(1960,1475) ; v1(2010,1475) 2090,1475
  Bottom Layer w10: v1(1960,1475) v1(2010,1475) ; v4(2105,1235) 2142,1272 2142,1463 2130,1475 v1(2105,1475)
PTA15: J4.13 STM32L431.50 | length 711.1
  Top Layer w10: STM32L431.50 1285.17,2075.17 1345,2135 1345,2223 J4.13
PTB0: J1.3 R201.1 R202.2 STM32L431.26 | length 1568.3
  Top Layer w10: v1(1165,1555) 1165,1480 1186.75,1458.25 STM32L431.26 ; J1.3 R202.2@2116.53,1630 ; R202.2 R201.1
  Bottom Layer w10: v1(1165,1555) 1395,1555 1420,1580 1528.89,1580 1530.89,1582 1549.11,1582 1556.11,1575 1886,1575 J1.3
PTB1: J1.4 STM32L431.27 | length 1403.3
  Top Layer w10: STM32L431.27 1206.43,1006.43 1215,997.87 v1(1215,995) 1217.67,992.33 1855,992.33 1870,1007.33 1870,1315 1945,1390 1975,1390 1985,1400 1985,1500 J1.4@1955,1530
PTB2: STM32L431.28
PTB3: J4.12 STM32L431.55 | length 610.4
  Top Layer w10: STM32L431.55 1186.75,2064.75 J4.12
PTB4: J4.11 STM32L431.56 | length 718.6
  Top Layer w10: STM32L431.56 1167.06,2072.06 1245,2150 1245,2210 1293,2258 J4.11
PTB5: J4.10 STM32L431.57 | length 585.3
  Top Layer w10: STM32L431.57 1147.38,2097.38 1193,2143 J4.10
PTB6: J4.9 STM32L431.58 | length 693.5
  Top Layer w10: STM32L431.58 1127.69,2142.69 1150,2165 1150,2228 J4.9
PTB7: J2.10 R4.1 STM32L431.59 | length 2213.3
  Top Layer w10: R4.1@448.47,535 450,533.47 v1(450,495) ; v1(755,380) 1090,380 1145,435 1145,523 J2.10 1039,725 987.58,725 987.58,1164.5 1071.32,1248.24 1071.32,1491.32 1108.01,1528.01 STM32L431.59
  Bottom Layer w10: v1(450,495) 725,495 750,470 750,380 v1(755,380)
PTB8: J2.11 R5.2 STM32L431.61 | length 1630.3
  Top Layer w10: R5.2 723.47,545 750,545 775,520 1050,520 ; STM32L431.61 1068.64,1539.64 1054.32,1525.32 1054.32,1255.28 970.58,1171.54 970.58,680.38 1050,600.96 1050,520 ; J2.11 1093,477 1050,520
PTB9: J2.12 R6.2 STM32L431.62 | length 1731.6
  Top Layer w10: R6.2 613.47,621.53 v1(620,615) ; v1@955,660 955,662.04 953.58,663.46 953.58,1178.58 1027,1252 1027,1252.5 1037.32,1262.83 1037.32,1537.32 1048.95,1548.95 STM32L431.62 ; v1(1040,655) 1093,602 J2.12
  Bottom Layer w10: v1@625,620 1040,620 1089,571 J2.12 ; v1(950,655) v1(1040,655)
PTB10: J3.8 STM32L431.29 | length 1244.9
  Top Layer w10: J3.8 448,1630 888.89,1630 985,1533.89 v1(985,1525) ; STM32L431.29 1245.8,1200.8 1253,1208 1253,1503 v1(1255,1505)
  Bottom Layer w10: v1(985,1525) 986.61,1525 1006.61,1505 v1(1255,1505)
PTB11: J3.9 STM32L431.30 | length 1352.3
  Top Layer w10: J3.9 448,1730 895,1730 985,1640 v1(985,1565) ; STM32L431.30 1265.49,1196.45 1270,1200.96 1270,1488.89 1281,1499.89 1281,1520
  Bottom Layer w10: v1(985,1565) 995,1565 1030,1530 v1(1275,1530)
PTB12: J4.5 STM32L431.33 | length 2147.5
  Top Layer w10: STM32L431.33 1519.28,1220.72 v1@1535,1205 ; v1(1683,1532) 1683,2028 1690,2035 ; v1(1695,1200) 1695,1245 v1(1710,1260)
  Bottom Layer w10: J4.5 945,2223 945,2070 975,2040 1568.23,2040 1569.23,2041 1699,2041 v1(1700,2040) ; v1(1540,1200) v1(1695,1200) ; v1(1683,1532) 1683,1430.04 1707.88,1405.16 1707.88,1262.12 v1(1710,1260)
PTB13: J4.6 STM32L431.34 | length 1836.2
  Top Layer w10: STM32L431.34 1530.41,1240.41 v1(1535,1245) ; v1(1659,1549) v1@1659,2074
  Bottom Layer w10: J4.6 993,2142 1055,2080 v1(1665,2080) ; v1(1535,1245) 1645,1245 1684,1284 1684,1405 1674,1415 1673.08,1415 1659,1429.08 v1(1659,1549)
PTB14: J4.8 STM32L431.35 | length 2117.8
  Top Layer w10: J4.8 1045,2219 1045,2310 1075,2340 1629.95,2340 1653,2316.95 1653,2146.15 1635,2128.15 v1(1635,1530) ; STM32L431.35 1515.09,1260.09 v1(1535,1280)
  Bottom Layer w10: v1(1535,1280) 1649.04,1280 1667,1297.96 1667,1397.04 1642,1422.04 1642,1423 1635,1430 v1(1635,1530)
PTB15: J4.7 STM32L431.36 | length 1848.6
  Top Layer w10: J4.7 1142,2320 1618.96,2320 1636,2302.96 1636,2153.19 1613,2130.19 v1(1613,1548) ; STM32L431.36 1500,1279.78 1500,1280 1530,1310 v1(1535,1310)
  Bottom Layer w10: v1(1535,1310) 1635,1310 1650,1325 1650,1390 1613,1427 v1(1613,1548)
PTC0: J2.17 STM32L431.8 | length 1891.2
  Top Layer w10: 374.96,1365 355,1345.04 355,625 v1(375,605) ; 375.96,1364 555,1364 569.2,1378.2 STM32L431.8 ; v1(480,470) 482.12,472.12 482.12,582.88 v1(480,585) ; v1(710,473) 791,473 J2.17
  Bottom Layer w10: v1(375,605) 470,605 480,595 v1(480,585) ; v1(480,470) 707,470 v1(710,473) ; J2.17@784,480 J2.17
PTC1: J3.1 STM32L431.9 | length 836.2
  Top Layer w10: v6(545,1335) 700.96,1335 724.48,1358.52 STM32L431.9
  Bottom Layer w10: J3.1 545,1026 v6(545,1335)
PTC2: J2.18 STM32L431.10 | length 1000.5
  Top Layer w10: v1(700,1110) 700,1310 728.83,1338.83 STM32L431.10 ; v1(705,910) 705,659 J2.18
  Bottom Layer w10: v1(700,1110) 702.12,1107.88 702.12,922.88 705,920
PTC3: J2.14 STM32L431.11 | length 1132.9
  Top Layer w10: v1(745,950) 745,650 775,620 944,620 J2.14 ; v1(745,1115) 725,1135 725,1300 744.15,1319.15 STM32L431.11
  Bottom Layer w10: 745,960 v1(745,1115)
PTC4: J1.7 STM32L431.24 | length 1217.9
  Top Layer w10: v1@1147.38,952.38 STM32L431.24 ; v1(1215,945) 1870,945 1905,980 1905,1012.67 1904,1013.67 1904,1196 J1.7@1938,1230
  Bottom Layer w10: v1(1150,945) 1155,950 1160,945 v1(1215,945)
PTC5: J1.10 STM32L431.25 | length 962.8
  Top Layer w10: STM32L431.25 1167.06,961.82 1205.89,923 1935,923 J1.10
PTC6: J2.3 STM32L431.37 | length 950.3
  Top Layer w10: STM32L431.37 1344.94,1299.46 1325.48,1280 1325.48,1223.72 1374,1175.2 1374,1071 v1@1415,1030 ; v1(1425,720) 1425,599.81 1436,588.81 1436,528 J2.3
  Bottom Layer w10: v1(1425,720) v1(1425,1030)
PTC7: J2.1 STM32L431.38 | length 1204.8
  Top Layer w10: STM32L431.38 1513.04,1319.15 1525.89,1332 1544.11,1332 1563,1313.11 1563,1181.85 1661.89,1082.96 v1(1661.89,1030)
  Bottom Layer w10: J2.1 1589,471 1540,520 1540,613.1 1519,634.09 1519,704.91 1545.09,731 1625.09,731 1659.09,765 1659.09,1027.21 v1(1661.89,1030)
PTC8: J2.2 STM32L431.39 | length 1043.7
  Top Layer w10: STM32L431.39 1393.61,1339 1508.85,1339 1518.85,1349 1556,1349 1580,1325 1580,1188.89 1693.89,1075 v1(1693.89,1026.11)
  Bottom Layer w10: J2.2 1693.89,671.89 v1(1693.89,1026.11)
PTC9: J2.4 STM32L431.40 | length 955
  Top Layer w10: v1(1375,1025) 1357,1043 1357,1168.15 1308.48,1216.67 1308.48,1340 1327,1358.52 STM32L431.40
  Bottom Layer w10: v1(1375,1025) 1400,1000 1400,635 1464,571 J2.4
PTC10: CH342.12 J1.1 STM32L431.51 | length 2354.9
  Top Layer w10: STM32L431.51 v1@1265.49,1849.51 ; J1.1 2065,1830 ; CH342.12 2074.4,650 v1(2145,650)
  Bottom Layer w10: v1(1260,1855) 1916,1855 J1.1 ; 2068,917 2162,823 2162,672.89 2145,655.89 v1(2145,650) ; 2068,919.67 2068,1818 v1(2075,1825)
PTC11: CH342.13 J1.2 STM32L431.52 | length 2216.9
  Top Layer w10: v1(1235,1830) 1244.2,1820.8 ; STM32L431.52 1245.8,1820.8 ; J1.2 v1(2040,1730) ; CH342.13 v1(2140,682)
  Bottom Layer w10: v1(1235,1830) 1885,1830 1900,1815 1900,1750 J1.2@1920,1730 ; v1(2040,1730) 2040,920.96 2140.96,820 2140,819.04 v1(2140,682)
PTC12: J2.6 STM32L431.53 | length 1143.7
  Top Layer w10: STM32L431.53 1226.12,1229.88 v1(1231,1225)
  Bottom Layer w10: v1(1231,1225) 1231,1200.11 1255,1176.11 1255,645 1280,620 1350,620 1393,577 J2.6
PTC13: STM32L431.2 T302.3 | length 4144.9
  Top Layer w10: v1(560,1760) v1(630,1760) v1(705,1760) ; v1@701.32,1496.32 STM32L431.2 ; v4(2105,1335) 2105,1435 v1@2150,1480 ; v1(2120,2090) 2155,2055 v1(2155,1920)
  Bottom Layer w10: v1(560,1760) 555,1765 555,1860 540,1875 380,1875 340,1915 340,2057.33 384.67,2102 537,2102 613,2178 613,2285.33 689.67,2362 1514.11,2362 1516.11,2360 2020,2360 2060,2320 2060,2216.89 2057.95,2214.83 2057.95,2157.22 2120,2095.17 v1(2120,2090) ; v1@630.2,1760.2 T302.3 ; v1(705,1760) 705,1500 v1(710,1495) ; v1(2155,1485) v1(2155,1920)
PTD2: J2.7 R205.1 STM32L431.54 | length 2297.9
  Top Layer w10: v1(1215,1185) 1206.43,1193.57 STM32L431.54 1206.43,1971.43 v1(1215,1980) ; v1(1920,1980) R205.1@1961.54,1980
  Bottom Layer w10: v1(1215,1185) 1220,1185 1237,1168 1237,527 J2.7 ; v1(1215,1980) v1(1920,1980)
PTH0: J3.5 STM32L431.5 | length 562
  Top Layer w10: 507.26,1437.26 STM32L431.5
  Bottom Layer w10: J3.5 456,1326 500,1370 v1(500,1445)
PTH1: J3.6 STM32L431.6 | length 467.6
  Top Layer w10: J3.6@453.43,1417.57 STM32L431.6
RESET: J4.2 RESET.1 RESET.2 STM32L431.7 | length 3387.3
  Top Layer w10: 390,445 v1(410,445) ; RESET.1 430.8,445 v1(410,445) ; v1(605,440) 630.75,414.25 RESET.2 ; J4.2 793,2202 680,2315 525,2315 510,2300 510,2180.17 452.78,2122.95 387.94,2122.95 335,2070 335,1414.92 ; STM32L431.7 472.89,1397.89 457,1382 367.92,1382 335,1414.92 ; 335,1414.92 333,1412.92 333,457 345,445 v1(410,445)
  Bottom Layer w10: v1(410,445) v1@600,445
SWD_CLK: J2.5 P8.3 STM32L431.49 | length 1402.1
  Top Layer w10: STM32L431.49 1304.86,1559.86 1298,1553 1298,1492.85 1290,1484.85 1290,1211.11 1340,1161.11 v1(1340,1020) ; P8.3 1315,393 J2.5 1345,519 1345,630 1360,645 v3(1360,695) 1385,720 1385,765 1330,820 v1(1330,900)
  Bottom Layer w10: v1(1330,900) 1330,1010 v1(1340,1020)
SWD_DIO: J2.8 P8.2 STM32L431.46 | length 1990.7
  Top Layer w10: v1(1120,1050) 1120,690 1140,670 1270,670 v3(1295,695) ; v1(1155,1190) v1(1155,1340) ; P8.2 1242,352 1242,520 J2.8 ; J2.8@1295,573 1295,670 ; STM32L431.46 1491.63,1476.63 1503,1488 1503,1489.11 1518.89,1505 v1(1570,1505)
  Bottom Layer w10: v1(1120,1050) 1155,1085 v1(1155,1190) ; v1(1155,1340) 1550,1340 1570,1360 v1(1570,1505)
VBAT: STM32L431.1
pads on no net: CH342.1 CH342.9 CH342.10 CH342.11 CH342.14 CH342.15 CH342.16 CH342.17 CH342.18 CH342.19 CH342.22 CH342.23 CH342.24 E1.3 E1.5 E1.6 E1.10 E1.12 E1.13 E1.14 E1.15 E1.17 E1.18 E1.19 E1.20 E1.21 E1.22 J2.9 J3.4 J4.1 S1.0 T301.3 T301.4 T302.4 TYPE_C. TYPE_C.1 TYPE_C.2 TYPE_C.3 TYPE_C.4 TYPE_C.A5 TYPE_C.A8 TYPE_C.B5 TYPE_C.B8
copper on no net:
  other v5: 2130,325 400,340 2125,2185 425,2190
  other v6: 525,815

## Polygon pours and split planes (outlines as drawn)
NetP203_1 on Top Layer "Bottom Layer-No Net 1" (solid, remove dead copper, pour order 6): 1675,2350 2050,2350 2050,2115 1675,2115
GND on Bottom Layer "Bottom Layer-No Net" (solid, remove dead copper, pour order 5): 315,1890 315,300 315,280 325,270 330,265 330,255 340,255 345,250 365,230 380,230 441.07,230 445,226.07 450.02,231.08 2125.67,231.08 2160.52,231.08 2165.46,236.02 2185,255.56 2185,260 2185,261.47 2205.06,281.53 2205,550 2205,2224.82 2200.04,2229.77 2183.66,2246.15 2183.66,2265.48 2183.66,2277.86 2134.9,2326.63 2098.3,2363.23 2080.78,2363.23 2080.78,2369.22 2080,2370 2067.28,2382.72 2018.43,2382.72 589.78,2382.72 588.96,2383.53 575.42,2370 530,2370 515,2370 495,2350 493.06,2348.06 442.53,2327.13 360.25,2226.87 340.92,2207.55 315.25,2181.87 330,2170 315.25,1880.03

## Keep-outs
Keep-Out Layer:
  lines w10: 315.25,2071.9 314.98,310 ccw(c394.27,309.95) 393.9,230.67 ; 315.3,2071.9 cw(c624.15,2071.15) 625,2380 ; 625,2381 2003.11,2381 ; 730,231.08 2125.67,231.08 ccw(c2125.72,310.36) 2205,310 2205.28,2175.89 ; 2004.05,2381 cw(c2003.11,2176.01) 2208.1,2175.89

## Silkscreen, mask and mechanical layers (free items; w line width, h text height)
Top Overlay:
  drawing of 1284 lines, arcs and shapes, not listed
  text "53" at 778,2329 h60
  text "33" at 887,2329 h60
  text "31" at 981,2329 h60
  text "29" at 1080,2329 h60
  text "27" at 1182,2329 h60
  text "24" at 1271,2329 h60
  text "22" at 1368,2329 h60
  text "15" at 1468,2329 h60
  text "64" at 1569,2329 h60
  text "金葫芦" at 1845,2270 h70
  text "5V" at 515,2175 h60
  text "RESET" at 590,2145 h60
  text "GND" at 560,2085 h60
  text "16" at 1470,2075 h60
  text "67" at 1566,2074 h60
  text "23" at 1262,2073 h60
  text "25" at 1174,2071 h60
  text "50" at 765,2070 h60
  text "32" at 865,2070 h60
  text "30" at 970,2070 h60
  text "28" at 1075,2070 h60
  text "21" at 1365,2070 h60
  text "3.3V" at 555,1955 h60
  text "14" at 2001,1815 h50
  text "37" at 330,1810 h60
  text "SD-20-21  202011" at 730,1715 h35
  text "13" at 2000,1710 h50
  text "38" at 333,1703 h60
  text "AHL-STM32L431-WiFi-2" at 725,1665 h35
  text "12" at 1999,1613 h50
  text "39" at 333,1610 h60
  text "11" at 2000,1518 h50
  text "40" at 329,1503 h60
  text "10" at 1997,1424 h50
  text "41" at 332,1411 h60
  text "69" at 2150,1325 h50
  text "8" at 2002,1316 h50
  text "42" at 329,1309 h60
  text "70" at 2150,1220 h50
  text "7" at 2005,1217 h50
  text "43" at 325,1195 h70
  text "9" at 2000,1121 h50
  text "71" at 2150,1120 h50
  text "44" at 329,1106 h60
  text "72" at 2150,1020 h50
  text "19" at 1997,1013 h50
  text "45" at 330,1006 h60
  text "73" at 2150,920 h50
  text "6" at 1998,912 h50
  text "46" at 330,905 h60
  text "GND" at 1440,725 h50
  text "3V3" at 1530,725 h50
  text "5V" at 1619.09,725 h50
  text "49" at 961,631 h60
  text "56" at 1169,631 h60
  text "67" at 875,630 h60
  text "54" at 1069,630 h60
  text "61" at 1376,630 h60
  text "48" at 761,629 h60
  text "58" at 1279,629 h60
  text "2" at 1474,629 h60
  text "3" at 1579,629 h60
  text "UART-Debug" at 1720,625 h45
  text "RGB" at 370,590 h70 r359.58
  text "UART-User" at 1720,585 h45
  text "UART-Debug" at 1735,425 h50
  text "55" at 1070,380 h50
  text "NC" at 1175,380 h50
  text "59" at 1275,380 h50
  text "62" at 1370,380 h50
  text "NC" at 965,375 h60
  text "67" at 860,370 h60
  text "5" at 1485,370 h60
  text "4" at 1575,370 h60
  text "47" at 767,368 h60
  text "UART-User" at 1740,365 h50
  text "SWD" at 970,300 h60
  text "金葫芦" at 1755,270 h70
  text "5V" at 1090,235 h50
  text "DIO" at 1185,235 h50
  text "CLK" at 1280,235 h50
  text "GND" at 1380,235 h50
Mechanical 1:
  lines w10: 393.9,230.67 730,231.08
